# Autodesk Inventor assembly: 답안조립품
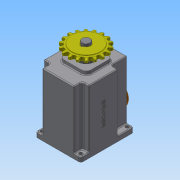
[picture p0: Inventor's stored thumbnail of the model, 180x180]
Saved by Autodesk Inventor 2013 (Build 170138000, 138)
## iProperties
Created: 2017-12
Part Number: 답안조립품
Document SubType Name: Assembly
Designer: Administrator
Author: Administrator
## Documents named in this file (17)
- C:\Users\Administrator\Desktop\371208V1017\답안조립품.iam
- C:\Users\Administrator\Desktop\371208V1017\멈춤나사 M3x8.ipt
- C:\Users\Administrator\Desktop\371208V1017\메인축.ipt
- C:\Users\Administrator\Desktop\371208V1017\베어링 608.ipt
- C:\Users\Administrator\Desktop\371208V1017\베어링 6003.ipt
- C:\Users\Administrator\Desktop\371208V1017\본체.ipt
- C:\Users\Administrator\Desktop\371208V1017\볼트 M4 x 10.ipt
- C:\Users\Administrator\Desktop\371208V1017\부시.ipt
- C:\Users\Administrator\Desktop\371208V1017\상부 캡.ipt
- C:\Users\Administrator\Desktop\371208V1017\서브축.ipt
- C:\Users\Administrator\Desktop\371208V1017\스프로킷.ipt
- C:\Users\Administrator\Desktop\371208V1017\슬라이더.ipt
- C:\Users\Administrator\Desktop\371208V1017\오일 실 8 22 7.ipt
- C:\Users\Administrator\Desktop\371208V1017\오일 실 17 32 8.ipt
- C:\Users\Administrator\Desktop\371208V1017\커버.ipt
- C:\Users\Administrator\Desktop\371208V1017\키 5 x 5 x 18.ipt
- C:\Users\Administrator\Desktop\371208V1017\가변스프링.ipt
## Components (1 placed, 1 different names)
1. 가변스프링:1
